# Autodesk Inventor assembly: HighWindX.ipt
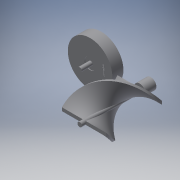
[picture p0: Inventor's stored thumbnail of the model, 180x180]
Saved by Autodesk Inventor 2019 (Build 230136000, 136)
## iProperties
Created: 2018-12
Part Number: HighWindX.ipt
Document SubType Name: Assembly
Designer: Patel Family
Author: Patel Family
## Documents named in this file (3)
- A:\Documents\Inventor Files\HighWindX.ipt.iam
- A:\Documents\Inventor Files\HighWindX Blade.ipt
- A:\Documents\Inventor Files\HighWindX Motor.ipt
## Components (2 placed, 2 different names)
1. HighWindX Blade:1
2. HighWindX Motor:1
